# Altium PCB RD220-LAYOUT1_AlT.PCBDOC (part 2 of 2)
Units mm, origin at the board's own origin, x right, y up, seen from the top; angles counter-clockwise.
Board outline 250 x 145 mm, 4 copper layers (TOP, Mid-Layer 1, Mid-Layer 2, BOTTOM), stack 0.711 mm thick; 98 components, 44 nets, 237 pads, 371 vias.
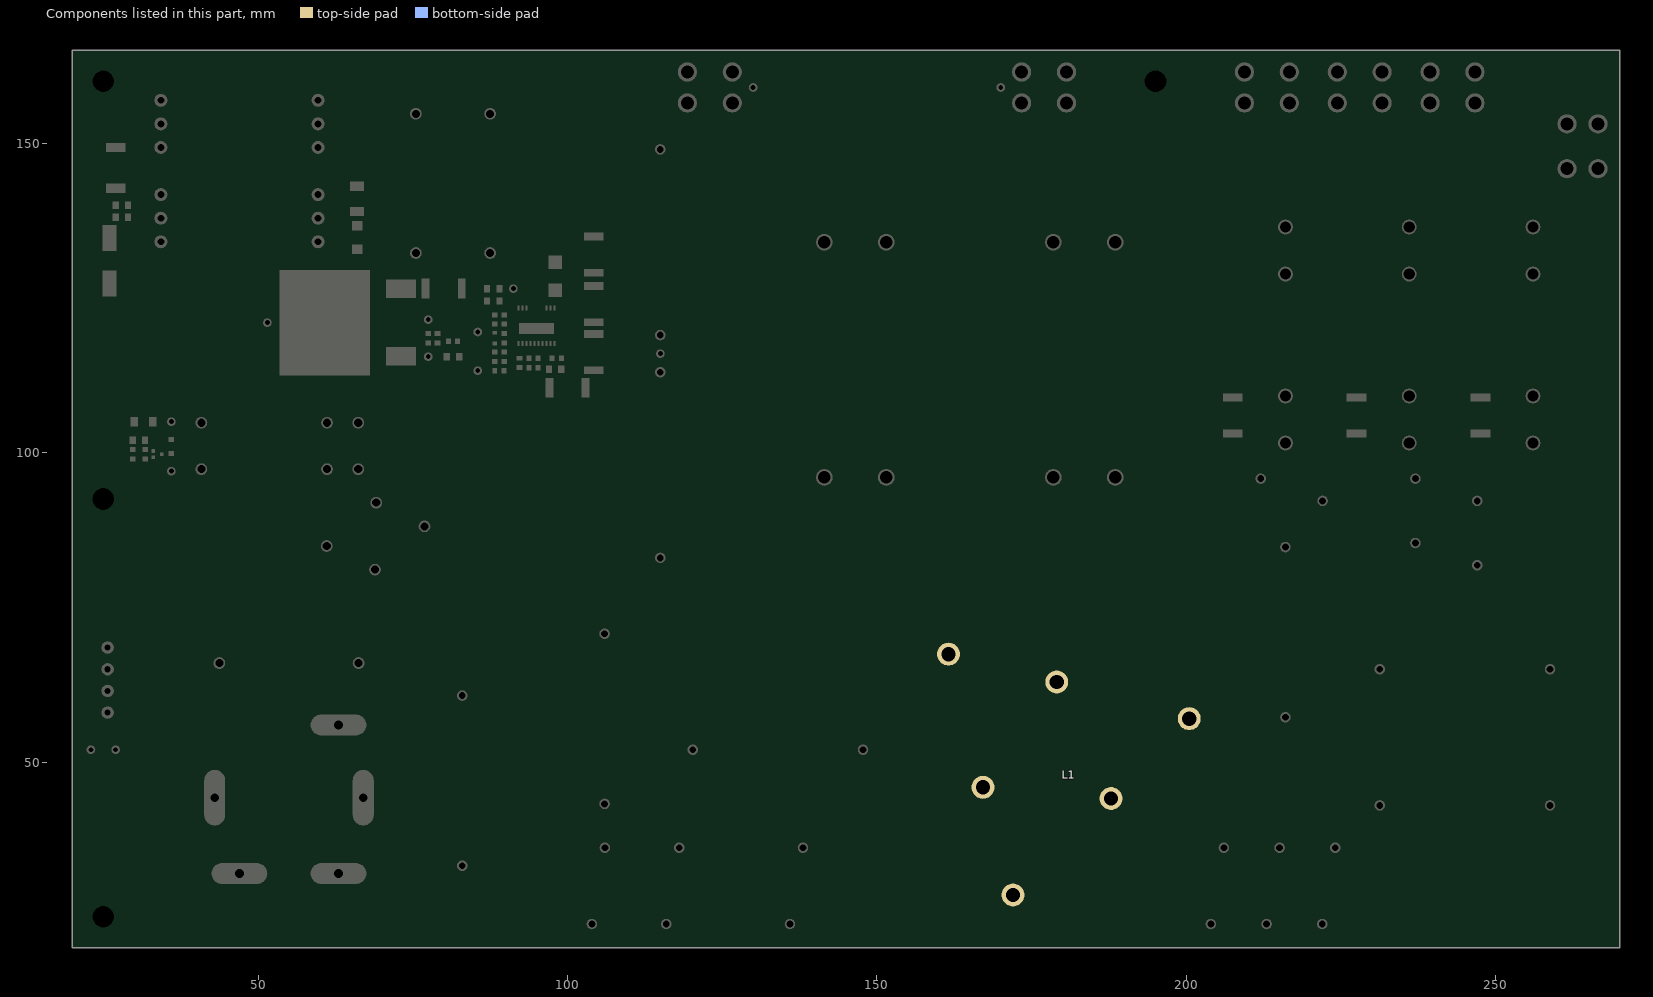
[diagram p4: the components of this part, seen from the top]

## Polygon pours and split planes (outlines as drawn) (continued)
VP_DC on BOTTOM "BOTTOM146" (solid, pour order 17): 73.5,152.3 cw(c73.5,152.8) 73,152.8 73,156.7 cw(c73.5,156.7) 73.5,157.2 88.453,157.2 cw(c88.453,157.05) 88.559,157.156 89.906,155.809 cw(c89.8,155.703) 89.95,155.703 89.95,152.8 cw(c89.45,152.8) 89.45,152.3
GND_DC on BOTTOM "BOTTOM147" (solid, pour order 18): 24 vertices, not listed, extent 73.25,126.7 101.5,134.5
SIGN00122 on BOTTOM "BOTTOM148" (solid, pour order 19): 47 vertices, not listed, extent 49.5,38.5 78,67.44
GND_F on BOTTOM "BOTTOM149" (solid, pour order 20): 21 vertices, not listed, extent 102.1,21 163.759,28.999
L1r on BOTTOM "BOTTOM150" (solid, pour order 21): 17 vertices, not listed, extent 134.45,33.393 139.9,37.906
L2r on BOTTOM "BOTTOM151" (solid, pour order 22): 113.95,33.4 cw(c113.95,33.55) 113.8,33.55 113.8,37.756 cw(c113.95,37.756) 113.95,37.906 116.839,37.906 116.843,37.906 119.257,37.906 cw(c119.257,37.756) 119.348,37.875 cw(c118.05,36.161) 119.877,37.294 cw(c119.75,37.215) 119.9,37.215 119.9,35.108 119.9,35.104 119.9,33.55 cw(c119.75,33.55) 119.75,33.4
GND_DC on BOTTOM "BOTTOM152" (solid, pour order 23): 97 vertices, not listed, extent 64.17,85.5 145.15,164
M on BOTTOM "BOTTOM153" (solid, pour order 24): 35 vertices, not listed, extent 112.65,93.15 181.35,136.85
L1r on BOTTOM "BOTTOM154" (solid, pour order 25): 57 vertices, not listed, extent 39.9,21 171,64.4
L3f on BOTTOM "BOTTOM155" (solid, pour order 26): 22 vertices, not listed, extent 168.5,26 185.345,35.375
L2r on BOTTOM "BOTTOM156" (solid, pour order 27): 64 vertices, not listed, extent 57.2,53.005 183,73.6
VP_DC on BOTTOM "BOTTOM157" (solid, pour order 28): 77 vertices, not listed, extent 39.9,38.5 193.25,164
L3r on BOTTOM "BOTTOM158" (solid, pour order 29): 48 vertices, not listed, extent 102.45,29.8 193.108,55.2
L2f on BOTTOM "BOTTOM159" (solid, pour order 30): 19 vertices, not listed, extent 202.45,33.4 207.95,38.05
L1f on BOTTOM "BOTTOM160" (solid, pour order 31): 211.6,33.4 cw(c211.6,33.55) 211.45,33.55 211.45,37.9 cw(c211.6,37.9) 211.6,38.05 214.034,38.05 214.036,38.05 215.757,38.05 cw(c215.757,38) 215.792,38.035 216.885,36.942 cw(c216.85,36.907) 216.9,36.907 216.9,35.08 216.9,35.077 216.9,33.55 cw(c216.75,33.55) 216.75,33.4
L1f on BOTTOM "BOTTOM161" (solid, pour order 32): 234.9,83.15 cw(c234.9,83.3) 234.75,83.3 234.75,89.4 cw(c234.9,89.4) 234.9,89.55 238.8,89.55 cw(c238.8,89.4) 238.95,89.4 238.95,86.511 238.95,86.509 238.95,84.291 238.95,84.289 238.95,83.3 cw(c238.8,83.3) 238.8,83.15
L1f on BOTTOM "BOTTOM162" (solid, pour order 33): 58 vertices, not listed, extent 157.71,62.479 233.2,112.35
L1 on BOTTOM "BOTTOM163" (solid, pour order 34): 33 vertices, not listed, extent 207.25,125.65 218.75,164
L2 on BOTTOM "BOTTOM164" (solid, pour order 35): 41 vertices, not listed, extent 222.25,125.65 238.95,164
L2f on BOTTOM "BOTTOM165" (solid, pour order 36): 74 vertices, not listed, extent 196.608,41.05 246.7,112.35
GND_F on BOTTOM "BOTTOM166" (solid, pour order 37): 62 vertices, not listed, extent 182.044,21 269,164
L3 on BOTTOM "BOTTOM167" (solid, pour order 38): 49 vertices, not listed, extent 237.25,125.65 260.2,164
L3f on BOTTOM "BOTTOM168" (solid, pour order 39): 102 vertices, not listed, extent 179.091,29.8 260.2,112.35
VDD20_A on BOTTOM "BOTTOM138" (solid, pour order 9): 28.25,133.45 cw(c28.25,134) 27.7,134 27.7,135.5 cw(c28.25,135.5) 28.25,136.05 29.75,136.05 cw(c29.75,135.5) 30.3,135.5 30.3,134 cw(c29.75,134) 29.75,133.45
VDD20_A on BOTTOM "BOTTOM139" (solid, pour order 10): 26.75,100.2 cw(c26.75,100.75) 26.2,100.75 26.2,102.25 cw(c26.75,102.25) 26.75,102.8 28.25,102.8 cw(c28.25,102.25) 28.8,102.25 28.8,100.75 cw(c28.25,100.75) 28.25,100.2
GND_A on BOTTOM "BOTTOM141" (solid, pour order 12): 19 vertices, not listed, extent 21,30 43.8,147.96
VDD20_A on BOTTOM "BOTTOM142" (solid, pour order 13): 22.277,50.7 cw(c22.277,50.85) 22.198,50.722 ccw(c21.75,50) 22.102,50.774 cw(c22.164,50.91) 22.062,50.8 cw(c22.062,50.95) 22.016,50.808 ccw(c21.75,50) 21.92,50.833 cw(c21.95,50.98) 21.8,50.98 cw(c21.85,51.121) 21.7,51.121 21.7,55.3 cw(c22.2,55.3) 22.2,55.8 23.9,55.8 cw(c23.9,55.3) 24.4,55.3 24.4,51.2 cw(c23.9,51.2) 23.9,50.7
no net on Top Solder "TOPSOLDER169" (solid, pour order 0): 164,24.3 cw(c164,25) 164,25.7 186,25.7 cw(c186,25) 186,24.3
no net on Top Solder "TOPSOLDER170" (solid, pour order 0): 193.05,160 ccw(c195,160) 196.95,160 ccw(c195,160)
no net on Top Solder "TOPSOLDER171" (solid, pour order 0): 23.05,160 ccw(c25,160) 26.95,160 ccw(c25,160)
no net on Top Solder "TOPSOLDER172" (solid, pour order 0): 23.05,92.5 ccw(c25,92.5) 26.95,92.5 ccw(c25,92.5)
no net on Top Solder "TOPSOLDER173" (solid, pour order 0): 23.05,25 ccw(c25,25) 26.95,25 ccw(c25,25)
no net on Bottom Solder "BOTTOMSOLDER174" (solid, pour order 0): 164,24.3 cw(c164,25) 164,25.7 186,25.7 cw(c186,25) 186,24.3
no net on Bottom Solder "BOTTOMSOLDER175" (solid, pour order 0): 253.5,128.85 ccw(c256,128.85) 258.5,128.85 ccw(c256,128.85)
no net on Bottom Solder "BOTTOMSOLDER176" (solid, pour order 0): 233.5,128.85 ccw(c236,128.85) 238.5,128.85 ccw(c236,128.85)
no net on Bottom Solder "BOTTOMSOLDER177" (solid, pour order 0): 213.5,136.45 ccw(c216,136.45) 218.5,136.45 ccw(c216,136.45)
no net on Bottom Solder "BOTTOMSOLDER178" (solid, pour order 0): 213.5,128.85 ccw(c216,128.85) 218.5,128.85 ccw(c216,128.85)
no net on Bottom Solder "BOTTOMSOLDER179" (solid, pour order 0): 238.395,137.166 cw(c236,136.45) 236.716,138.845
no net on Bottom Solder "BOTTOMSOLDER180" (solid, pour order 0): 233.5,101.55 ccw(c236,101.55) 238.5,101.55 ccw(c236,101.55)
no net on Bottom Solder "BOTTOMSOLDER181" (solid, pour order 0): 255.411,111.58 cw(c256,109.15) 253.57,109.739
no net on Bottom Solder "BOTTOMSOLDER182" (solid, pour order 0): 258.458,101.093 ccw(c265,92.5) 256.443,99.09 cw(c256,101.55) 258.458,101.093
no net on Bottom Solder "BOTTOMSOLDER183" (solid, pour order 0): 235.411,111.58 cw(c236,109.15) 233.57,109.739
no net on Bottom Solder "BOTTOMSOLDER184" (solid, pour order 0): 238.95,94.677 cw(c237,95.8) 238.95,96.923
no net on Bottom Solder "BOTTOMSOLDER185" (solid, pour order 0): 213.5,109.15 ccw(c216,109.15) 218.5,109.15 ccw(c216,109.15)
no net on Bottom Solder "BOTTOMSOLDER186" (solid, pour order 0): 213.5,101.55 ccw(c216,101.55) 218.5,101.55 ccw(c216,101.55)
no net on Bottom Solder "BOTTOMSOLDER187" (solid, pour order 0): 209.75,95.8 ccw(c212,95.8) 214.25,95.8 ccw(c212,95.8)
no net on Bottom Solder "BOTTOMSOLDER188" (solid, pour order 0): 213.75,84.75 ccw(c216,84.75) 218.25,84.75 ccw(c216,84.75)
no net on Bottom Solder "BOTTOMSOLDER189" (solid, pour order 0): 244.75,92.2 ccw(c247,92.2) 249.25,92.2 ccw(c247,92.2)
no net on Bottom Solder "BOTTOMSOLDER190" (solid, pour order 0): 238.95,84.277 cw(c237,85.4) 238.95,86.522
no net on Bottom Solder "BOTTOMSOLDER191" (solid, pour order 0): 260.2,63.28 cw(c258.75,65) 260.2,66.72
no net on Bottom Solder "BOTTOMSOLDER192" (solid, pour order 0): 213.75,57.25 ccw(c216,57.25) 218.25,57.25 ccw(c216,57.25)
no net on Bottom Solder "BOTTOMSOLDER193" (solid, pour order 0): 230.128,63.05 cw(c231.25,65) 231.835,67.173 233.2,65.808 233.2,64.192 232.058,63.05
no net on Bottom Solder "BOTTOMSOLDER194" (solid, pour order 0): 202.331,59.55 cw(c200.458,57.018) 198.584,59.55
no net on Bottom Solder "BOTTOMSOLDER195" (solid, pour order 0): 230.442,41.05 229.077,42.415 cw(c231.25,43) 233.423,42.415 232.058,41.05
no net on Bottom Solder "BOTTOMSOLDER196" (solid, pour order 0): 221.9,36.161 ccw(c224.05,36.161) 226.2,36.161 ccw(c224.05,36.161)
no net on Bottom Solder "BOTTOMSOLDER197" (solid, pour order 0): 260.2,41.28 cw(c258.75,43) 260.2,44.72
no net on Bottom Solder "BOTTOMSOLDER198" (solid, pour order 0): 215.777,38.05 216.9,36.927 216.9,35.066 cw(c215.05,36.161) 214.023,38.05
no net on Bottom Solder "BOTTOMSOLDER199" (solid, pour order 0): 207.077,38.05 cw(c206.05,36.161) 207.95,37.167 207.95,35.155 cw(c206.05,36.161) 205.023,38.05
no net on Bottom Solder "BOTTOMSOLDER200" (solid, pour order 0): 175.896,62.954 ccw(c179.046,62.954) 182.196,62.954 ccw(c179.046,62.954)
no net on Bottom Solder "BOTTOMSOLDER201" (solid, pour order 0): 158.41,67.44 ccw(c161.56,67.44) 164.71,67.44 ccw(c161.56,67.44)
no net on Bottom Solder "BOTTOMSOLDER202" (solid, pour order 0): 165.783,43.079 cw(c167.124,45.929) 169.947,44.53 166.442,43.079
no net on Bottom Solder "BOTTOMSOLDER203" (solid, pour order 0): 186.318,41.353 cw(c187.83,44.117) 190.853,43.232
no net on Bottom Solder "BOTTOMSOLDER204" (solid, pour order 0): 170.122,26 cw(c171.982,28.542) 169.652,30.662 172.131,31.689 cw(c171.982,28.542) 174.354,26.469 173.25,26
no net on Bottom Solder "BOTTOMSOLDER205" (solid, pour order 0): 145.5,52 ccw(c147.75,52) 150,52 ccw(c147.75,52)
no net on Bottom Solder "BOTTOMSOLDER206" (solid, pour order 0): 118,52 ccw(c120.25,52) 122.5,52 ccw(c120.25,52)
no net on Bottom Solder "BOTTOMSOLDER207" (solid, pour order 0): 103.75,43.25 ccw(c106,43.25) 108.25,43.25 ccw(c106,43.25)
no net on Bottom Solder "BOTTOMSOLDER208" (solid, pour order 0): 103.75,70.75 ccw(c106,70.75) 108.25,70.75 ccw(c106,70.75)
no net on Bottom Solder "BOTTOMSOLDER209" (solid, pour order 0): 80.75,60.75 ccw(c83,60.75) 85.25,60.75 ccw(c83,60.75)
no net on Bottom Solder "BOTTOMSOLDER210" (solid, pour order 0): 60.2,53 cw(c60.2,56) 60.2,59 65.8,59 cw(c65.8,56) 65.8,53
no net on Bottom Solder "BOTTOMSOLDER211" (solid, pour order 0): 44.2,29 cw(c44.2,32) 44.2,35 49.8,35 cw(c49.8,32) 52.7,32.768 52.7,31.232 cw(c49.8,32) 49.8,29
no net on Bottom Solder "BOTTOMSOLDER212" (solid, pour order 0): 42.455,38.5 cw(c43,41.45) 40,41.45 40,47.05 cw(c43,47.05) 46,47.05 46,41.45 cw(c43,41.45) 43.545,38.5
no net on Bottom Solder "BOTTOMSOLDER213" (solid, pour order 0): 66.455,38.5 cw(c67,41.45) 64,41.45 64,47.05 cw(c67,47.05) 65.276,49.505 68.724,49.505 cw(c67,47.05) 70,47.05 70,41.45 cw(c67,41.45) 67.545,38.5
no net on Bottom Solder "BOTTOMSOLDER214" (solid, pour order 0): 41.5,66 ccw(c43.75,66) 46,66 ccw(c43.75,66)
no net on Bottom Solder "BOTTOMSOLDER215" (solid, pour order 0): 74.65,88.09 ccw(c76.9,88.09) 79.15,88.09 ccw(c76.9,88.09)
no net on Bottom Solder "BOTTOMSOLDER216" (solid, pour order 0): 63.17,103.839 cw(c61.15,104.83) 63.17,105.821
no net on Bottom Solder "BOTTOMSOLDER217" (solid, pour order 0): 63.17,96.339 cw(c61.15,97.33) 63.17,98.321
no net on Bottom Solder "BOTTOMSOLDER218" (solid, pour order 0): 64.17,105.821 cw(c66.19,104.83) 64.17,103.839
no net on Bottom Solder "BOTTOMSOLDER219" (solid, pour order 0): 63.17,84.028 cw(c61.1,84.91) 63.17,85.792
no net on Bottom Solder "BOTTOMSOLDER220" (solid, pour order 0): 65.986,95.089 cw(c66.19,97.33) 64.17,96.339 64.17,98.321 cw(c66.19,97.33) 68.17,96.262 ccw(c69.1,91.91) 65.986,95.089
no net on Bottom Solder "BOTTOMSOLDER221" (solid, pour order 0): 112.85,83 ccw(c115,83) 117.15,83 ccw(c115,83)
no net on Bottom Solder "BOTTOMSOLDER222" (solid, pour order 0): 138.85,96 ccw(c141.5,96) 144.15,96 ccw(c141.5,96)
no net on Bottom Solder "BOTTOMSOLDER223" (solid, pour order 0): 148.85,96 ccw(c151.5,96) 154.15,96 ccw(c151.5,96)
no net on Bottom Solder "BOTTOMSOLDER224" (solid, pour order 0): 175.85,96 ccw(c178.5,96) 181.15,96 ccw(c178.5,96)
no net on Bottom Solder "BOTTOMSOLDER225" (solid, pour order 0): 185.85,96 ccw(c188.5,96) 191.15,96 ccw(c188.5,96)
no net on Bottom Solder "BOTTOMSOLDER226" (solid, pour order 0): 185.85,134 ccw(c188.5,134) 191.15,134 ccw(c188.5,134)
no net on Bottom Solder "BOTTOMSOLDER227" (solid, pour order 0): 175.85,134 ccw(c178.5,134) 181.15,134 ccw(c178.5,134)
no net on Bottom Solder "BOTTOMSOLDER228" (solid, pour order 0): 148.85,134 ccw(c151.5,134) 154.15,134 ccw(c151.5,134)
no net on Bottom Solder "BOTTOMSOLDER229" (solid, pour order 0): 138.85,134 ccw(c141.5,134) 144.15,134 ccw(c141.5,134)
no net on Bottom Solder "BOTTOMSOLDER230" (solid, pour order 0): 112.85,149 ccw(c115,149) 117.15,149 ccw(c115,149)
no net on Bottom Solder "BOTTOMSOLDER231" (solid, pour order 0): 85.25,154.75 ccw(c87.5,154.75) 89.75,154.75 ccw(c87.5,154.75)
no net on Bottom Solder "BOTTOMSOLDER232" (solid, pour order 0): 73.25,154.75 ccw(c75.5,154.75) 77.75,154.75 ccw(c75.5,154.75)
no net on Bottom Solder "BOTTOMSOLDER233" (solid, pour order 0): 85.25,132.25 ccw(c87.5,132.25) 89.75,132.25 ccw(c87.5,132.25)
no net on Bottom Solder "BOTTOMSOLDER234" (solid, pour order 0): 73.25,132.25 ccw(c75.5,132.25) 77.75,132.25 ccw(c75.5,132.25)
no net on Bottom Solder "BOTTOMSOLDER235" (solid, pour order 0): 57.618,140.6 cw(c59.7,141.69) 61.782,140.6
no net on Bottom Solder "BOTTOMSOLDER236" (solid, pour order 0): 57.8,30.2 cw(c60.2,32) 60.2,35 65.8,35 cw(c65.8,32) 68.2,30.2
no net on Bottom Solder "BOTTOMSOLDER237" (solid, pour order 0): 255.149,138.801 ccw(c256.721,141.815) 255.42,138.674 258.272,137.493 cw(c256,136.45) 255.149,138.801
no net on Bottom Solder "BOTTOMSOLDER238" (solid, pour order 0): 116.525,156.5 ccw(c119.375,156.5) 122.225,156.5 ccw(c119.375,156.5)
no net on Bottom Solder "BOTTOMSOLDER239" (solid, pour order 0): 123.775,156.5 ccw(c126.625,156.5) 129.475,156.5 ccw(c126.625,156.5)
no net on Bottom Solder "BOTTOMSOLDER240" (solid, pour order 0): 170.525,156.5 ccw(c173.375,156.5) 176.225,156.5 ccw(c173.375,156.5)
no net on Bottom Solder "BOTTOMSOLDER241" (solid, pour order 0): 177.775,156.5 ccw(c180.625,156.5) 183.475,156.5 ccw(c180.625,156.5)
no net on Bottom Solder "BOTTOMSOLDER242" (solid, pour order 0): 247.993,164 cw(c246.625,161.5) 248.6,163.555 248.6,159.445 cw(c246.625,161.5) 245.257,164
no net on Bottom Solder "BOTTOMSOLDER243" (solid, pour order 0): 248.6,154.445 cw(c246.625,156.5) 248.6,158.555
no net on Bottom Solder "BOTTOMSOLDER244" (solid, pour order 0): 237.25,163.399 cw(c239.375,161.5) 238.007,164 240.743,164 cw(c239.375,161.5) 237.25,159.601
no net on Bottom Solder "BOTTOMSOLDER245" (solid, pour order 0): 237.25,158.399 cw(c239.375,156.5) 237.25,154.601
no net on Bottom Solder "BOTTOMSOLDER246" (solid, pour order 0): 232.993,164 cw(c231.625,161.5) 233.75,163.399 233.75,159.601 cw(c231.625,161.5) 230.257,164
no net on Bottom Solder "BOTTOMSOLDER247" (solid, pour order 0): 233.75,154.601 cw(c231.625,156.5) 233.75,158.399
no net on Bottom Solder "BOTTOMSOLDER248" (solid, pour order 0): 222.25,163.399 cw(c224.375,161.5) 223.007,164 225.743,164 cw(c224.375,161.5) 222.25,159.601
no net on Bottom Solder "BOTTOMSOLDER249" (solid, pour order 0): 222.25,158.399 cw(c224.375,156.5) 222.25,154.601
no net on Bottom Solder "BOTTOMSOLDER250" (solid, pour order 0): 217.993,164 cw(c216.625,161.5) 218.75,163.399 218.75,159.601 cw(c216.625,161.5) 215.257,164
no net on Bottom Solder "BOTTOMSOLDER251" (solid, pour order 0): 218.75,154.601 cw(c216.625,156.5) 218.75,158.399
no net on Bottom Solder "BOTTOMSOLDER252" (solid, pour order 0): 207.25,163.399 cw(c209.375,161.5) 208.007,164 210.743,164 cw(c209.375,161.5) 207.25,159.601
no net on Bottom Solder "BOTTOMSOLDER253" (solid, pour order 0): 207.25,158.399 cw(c209.375,156.5) 207.25,154.601
no net on Bottom Solder "BOTTOMSOLDER254" (solid, pour order 0): 181.993,164 cw(c180.625,161.5) 179.257,164
no net on Bottom Solder "BOTTOMSOLDER255" (solid, pour order 0): 174.743,164 cw(c173.375,161.5) 172.007,164
no net on Bottom Solder "BOTTOMSOLDER256" (solid, pour order 0): 127.993,164 cw(c126.625,161.5) 125.257,164
no net on Bottom Solder "BOTTOMSOLDER257" (solid, pour order 0): 120.743,164 cw(c119.375,161.5) 118.007,164
no net on Bottom Solder "BOTTOMSOLDER258" (solid, pour order 0): 193.05,160 ccw(c195,160) 196.95,160 ccw(c195,160)
no net on Bottom Solder "BOTTOMSOLDER259" (solid, pour order 0): 23.05,160 ccw(c25,160) 26.95,160 ccw(c25,160)
no net on Bottom Solder "BOTTOMSOLDER260" (solid, pour order 0): 23.05,92.5 ccw(c25,92.5) 26.95,92.5 ccw(c25,92.5)
no net on Bottom Solder "BOTTOMSOLDER261" (solid, pour order 0): 23.05,25 ccw(c25,25) 26.95,25 ccw(c25,25)
no net on Bottom Solder "BOTTOMSOLDER262" (solid, pour order 0): 80.75,33.25 ccw(c83,33.25) 85.25,33.25 ccw(c83,33.25)
no net on Bottom Solder "BOTTOMSOLDER263" (solid, pour order 0): 114.183,117.011 cw(c115,119) 115.817,117.011 ccw(c115,116) 114.183,117.011
no net on Bottom Solder "BOTTOMSOLDER264" (solid, pour order 0): 114.183,114.989 ccw(c115,116) 115.817,114.989 cw(c115,113) 114.183,114.989
no net on Bottom Solder "BOTTOMSOLDER265" (solid, pour order 0): 135.901,36.113 ccw(c135.25,37) 136.281,37.383 cw(c138.05,36.161) 136.793,37.906 138.922,37.906 139.9,36.927 139.9,35.066 cw(c138.05,36.161) 135.901,36.113
no net on Bottom Solder "BOTTOMSOLDER266" (solid, pour order 0): 115.901,36.113 ccw(c115.25,37) 116.281,37.383 cw(c118.05,36.161) 116.793,37.906 119.307,37.906 cw(c118.05,36.161) 119.9,37.257 119.9,35.066 cw(c118.05,36.161) 115.901,36.113
no net on Bottom Solder "BOTTOMSOLDER267" (solid, pour order 0): 103.901,36.113 ccw(c103.25,37) 104.281,37.383 cw(c106.05,36.161) 103.901,36.113
no net on Bottom Solder "BOTTOMSOLDER268" (solid, pour order 0): 244.75,81.8 ccw(c247,81.8) 249.25,81.8 ccw(c247,81.8)
no net on Bottom Solder "BOTTOMSOLDER269" (solid, pour order 0): 220.05,93.322 cw(c222,92.2) 220.05,91.078
no net on Bottom Solder "BOTTOMSOLDER270" (solid, pour order 0): 67.979,67.44 cw(c66.25,66) 68.325,66.869 ccw(c69,66) 68.325,65.131 cw(c66.25,66) 64.521,67.44

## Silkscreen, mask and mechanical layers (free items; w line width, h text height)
Top Overlay:
  lines w0.2: 88.5,109.2 88.5,112.3 ; 85.9,97.3 89.5,97.3 89.5,99.2 89.1,99.2 89.1,109.2 86.1,109.2 85.9,109.2 85.9,97.3 ; 87.2,112.3 90.6,112.3 90.6,123.2 87.4,123.2 87.4,120.8 87.2,120.8 87.2,112.3 ; 92.4,109.7 92.4,112.8 93,112.8 93,116.1 96,116.1 96,112.6 95.9,112.6 95.9,109.7 92.4,109.7
  text "L1" at 204.77,157.525 h1.8
  text "L2" at 219.77,157.525 h1.8
  text "L3" at 234.87,157.425 h1.8
  text "DC Output" at 143.685,157.225 h1.8
  text "-" at 115.7,156.8 h2
  text "+" at 182.9,156.8 h2
  text "AC Input" at 221.44,146.125 h1.8
  text "FG" at 262.02,140.3 h2
  text "SNS" at 73.24,120.46 h0.71
  text "Np" at 82.69,120.36 h0.71
  text "Na" at 50.59,118.26 h0.71
  text "FL3" at 212.84,117.74 h0.71 r90
  text "FL9" at 252.74,117.74 h0.71 r90
  text "FL6" at 232.74,117.64 h0.71 r90
  text "16A 500V" at 263.075,112.14 h1.8 r90
  text "16A 500V" at 223.975,111.54 h1.8 r90
  text "16A 500V" at 244.075,111.54 h1.8 r90
  text "FB" at 82.39,111.36 h0.71
  text "GATE" at 75.29,110.86 h0.71
  text "A20V" at 35.43,67.6 h0.89
  text "AGND" at 35.43,57.1 h0.89
  text "A20V" at 24.54,46.29 h0.71 r90
  text "AGND" at 28.29,46.29 h0.71 r90
  text "400V 3phase AC-DC" at 53.02,21.6 h2.2
Mechanical 3:
  lines w0.013: 20.006,20.006 270.006,20.006 270.006,165.006 20.006,165.006 20.006,20.006 ; 164.006,24.506 cw(c164.006,25.006) 164.006,25.506 186.006,25.506 cw(c186.006,25.006) 186.006,24.506 164.006,24.506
